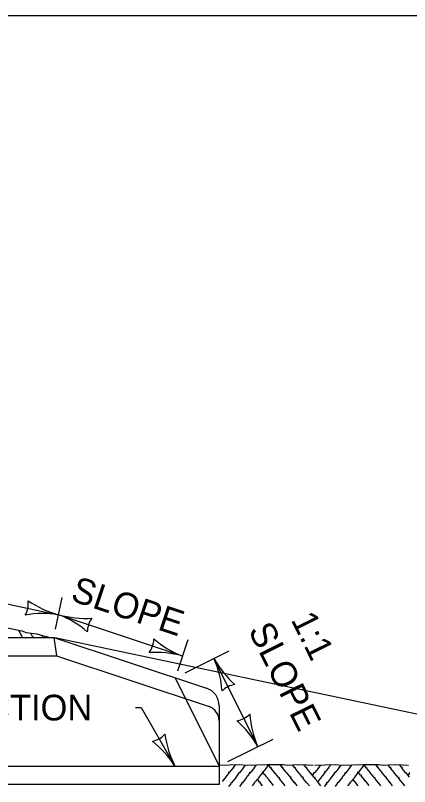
# Model space of a CAD drawing. Extents: x 49991.4 to 50022.1, y 49985 to 50011.4.
# Drawn here: x 50005.853 to 50006.771, y 49997.203 to 49998.999 of the extents above; entities that cross this region are included whole.
import ezdxf

# ---------------------------------------------------------------- set-up
doc = ezdxf.new("R2010")
doc.units = 0
for name, color, linetype in [('Level 1', 7, 'Continuous'), ('Level 2', 7, 'Continuous'), ('Level 3', 7, 'Continuous'), ('Level 4', 7, 'Continuous')]:
    doc.layers.add(name, color=color, linetype=linetype)

msp = doc.modelspace()

# ---------------------------------------------------------------- linework, layer by layer
at = {"layer": 'Level 1'}
for p, q in [((50003.702, 49997.5504), (50005.9421, 49997.5504)), ((50005.9421, 49997.5504), (50006.2981, 49997.4318)), ((50006.3273, 49997.3911), (50006.3273, 49997.208)), ((50006.3273, 49997.208), (50003.702, 49997.208))]:
    msp.add_line(p, q, dxfattribs=at)
msp.add_lwpolyline([(49999.3835, 49998.9992), (50016.7501, 49998.9992), (50016.7501, 49987.7988), (49999.3835, 49987.7988)], close=True, dxfattribs=at)
for points in [[(50005.7214, 49997.5944), (50005.7679, 49997.5866), (50005.785, 49997.5809), (50005.83, 49997.5731), (50005.8678, 49997.5653), (50005.8779, 49997.5617), (50005.9026, 49997.5584), (50005.9212, 49997.5532), (50005.9355, 49997.5494)], [(50005.8697, 49997.5486), (50005.8653, 49997.5572), (50005.866, 49997.559), (50005.8642, 49997.5593), (50005.8606, 49997.5668)], [(50005.8943, 49997.5486), (50005.8935, 49997.5506), (50005.8942, 49997.5522), (50005.8923, 49997.5526), (50005.8888, 49997.5602)], [(50005.9177, 49997.5486), (50005.9146, 49997.5552)], [(50006.3278, 49997.2526), (50006.375, 49997.2545), (50006.3929, 49997.2526), (50006.4385, 49997.2541), (50006.4769, 49997.2543), (50006.4876, 49997.2529), (50006.5126, 49997.2545), (50006.5318, 49997.2535), (50006.5465, 49997.2526)], [(50006.3658, 49997.2543), (50006.3598, 49997.2471), (50006.3605, 49997.2455), (50006.359, 49997.2455), (50006.3516, 49997.2361), (50006.3496, 49997.2361), (50006.35, 49997.2345), (50006.3422, 49997.2249), (50006.3422, 49997.2229), (50006.3406, 49997.2225), (50006.3344, 49997.2145)], [(50006.3882, 49997.2525), (50006.3827, 49997.2459), (50006.3836, 49997.2443), (50006.3821, 49997.2443), (50006.3746, 49997.2349), (50006.3726, 49997.2349), (50006.3728, 49997.2331), (50006.3652, 49997.2235), (50006.3652, 49997.2215), (50006.3636, 49997.2211), (50006.3562, 49997.2115), (50006.3545, 49997.2115), (50006.3548, 49997.2095), (50006.3496, 49997.2033)], [(50006.4139, 49997.2533), (50006.4079, 49997.246), (50006.4086, 49997.2445), (50006.4072, 49997.2445), (50006.3998, 49997.2351), (50006.3977, 49997.2351), (50006.398, 49997.2333), (50006.3905, 49997.2237), (50006.3905, 49997.222), (50006.3887, 49997.2213), (50006.3815, 49997.2119), (50006.3796, 49997.2117), (50006.38, 49997.21), (50006.3748, 49997.2034)], [(50006.4433, 49997.2541), (50006.4373, 49997.2469), (50006.438, 49997.2454), (50006.4367, 49997.2454), (50006.4292, 49997.2361), (50006.4274, 49997.2361), (50006.4276, 49997.2341), (50006.4199, 49997.2245), (50006.4199, 49997.2229), (50006.4182, 49997.2221), (50006.4109, 49997.2129), (50006.4092, 49997.2125), (50006.4094, 49997.2109), (50006.4043, 49997.2045)], [(50006.4817, 49997.2045), (50006.4769, 49997.2107), (50006.4754, 49997.2105), (50006.4757, 49997.2119), (50006.4682, 49997.2211), (50006.4686, 49997.2231), (50006.4667, 49997.2231), (50006.4592, 49997.2329), (50006.4574, 49997.2333), (50006.4572, 49997.2349), (50006.4498, 49997.2443), (50006.4499, 49997.246), (50006.4481, 49997.2461), (50006.443, 49997.2527)], [(50006.5092, 49997.2049), (50006.5036, 49997.2123), (50006.5018, 49997.2119), (50006.5022, 49997.2135), (50006.4948, 49997.2227), (50006.495, 49997.2245), (50006.4934, 49997.2249), (50006.4858, 49997.2345), (50006.4841, 49997.2347), (50006.4838, 49997.2365), (50006.4762, 49997.2459), (50006.4766, 49997.2477), (50006.4746, 49997.2477), (50006.4696, 49997.2543)], [(50006.5378, 49997.2045), (50006.5322, 49997.2115), (50006.5308, 49997.2113), (50006.531, 49997.2125), (50006.5236, 49997.222), (50006.524, 49997.2239), (50006.522, 49997.2241), (50006.5146, 49997.2335), (50006.5128, 49997.234), (50006.5126, 49997.2359), (50006.5051, 49997.2451), (50006.5052, 49997.2469), (50006.5036, 49997.2469), (50006.4985, 49997.2535)], [(50006.5483, 49997.2249), (50006.5412, 49997.2339), (50006.5396, 49997.2341), (50006.5393, 49997.2359), (50006.5316, 49997.2453), (50006.5321, 49997.2471), (50006.5302, 49997.2471), (50006.5249, 49997.2539)], [(50006.5639, 49997.2531), (50006.5579, 49997.246), (50006.5586, 49997.2445), (50006.5572, 49997.2445), (50006.5496, 49997.2351), (50006.5488, 49997.2351)], [(50006.5506, 49997.2526), (50006.5978, 49997.2545), (50006.6156, 49997.2526), (50006.6612, 49997.2541), (50006.6996, 49997.2543), (50006.7103, 49997.2529), (50006.7352, 49997.2545), (50006.7544, 49997.2535), (50006.7692, 49997.2526)], [(50006.5885, 49997.2543), (50006.5825, 49997.2471), (50006.5832, 49997.2455), (50006.5818, 49997.2455), (50006.5744, 49997.2361), (50006.5723, 49997.2361), (50006.5728, 49997.2345), (50006.5651, 49997.2249), (50006.5651, 49997.2229), (50006.5633, 49997.2225), (50006.5573, 49997.2145)], [(50006.611, 49997.2525), (50006.6056, 49997.2459), (50006.606, 49997.2443), (50006.6047, 49997.2443), (50006.5972, 49997.2349), (50006.5954, 49997.2349), (50006.5956, 49997.2331), (50006.5879, 49997.2235), (50006.5879, 49997.2215), (50006.5864, 49997.2211), (50006.579, 49997.2115), (50006.5772, 49997.2115), (50006.5776, 49997.2095), (50006.5723, 49997.2033)], [(50006.6366, 49997.2533), (50006.6306, 49997.246), (50006.6314, 49997.2445), (50006.6299, 49997.2445), (50006.6224, 49997.2351), (50006.6206, 49997.2351), (50006.6209, 49997.2333), (50006.6131, 49997.2237), (50006.6131, 49997.222), (50006.6116, 49997.2213), (50006.6042, 49997.2119), (50006.6023, 49997.2117), (50006.6028, 49997.21), (50006.5975, 49997.2034)], [(50006.666, 49997.2541), (50006.66, 49997.2469), (50006.6608, 49997.2454), (50006.6596, 49997.2454), (50006.6521, 49997.2361), (50006.6502, 49997.2361), (50006.6503, 49997.2341), (50006.6426, 49997.2245), (50006.6426, 49997.2229), (50006.641, 49997.2221), (50006.6336, 49997.2129), (50006.632, 49997.2125), (50006.6323, 49997.2109), (50006.627, 49997.2045)], [(50006.7046, 49997.2045), (50006.6998, 49997.2107), (50006.6982, 49997.2105), (50006.6986, 49997.2119), (50006.6911, 49997.2211), (50006.6914, 49997.2231), (50006.6896, 49997.2231), (50006.6821, 49997.2329), (50006.6803, 49997.2333), (50006.68, 49997.2349), (50006.6725, 49997.2443), (50006.6728, 49997.246), (50006.671, 49997.2461), (50006.6659, 49997.2527)], [(50006.7318, 49997.2049), (50006.7262, 49997.2123), (50006.7246, 49997.2119), (50006.725, 49997.2135), (50006.7175, 49997.2227), (50006.7178, 49997.2245), (50006.7162, 49997.2249), (50006.7085, 49997.2345), (50006.7067, 49997.2347), (50006.7066, 49997.2365), (50006.6989, 49997.2459), (50006.6992, 49997.2477), (50006.6974, 49997.2477), (50006.6923, 49997.2543)], [(50006.7606, 49997.2045), (50006.755, 49997.2115), (50006.7535, 49997.2113), (50006.7538, 49997.2125), (50006.7463, 49997.222), (50006.7468, 49997.2239), (50006.7448, 49997.2241), (50006.7373, 49997.2335), (50006.7355, 49997.234), (50006.7352, 49997.2359), (50006.7277, 49997.2451), (50006.7282, 49997.2469), (50006.7262, 49997.2469), (50006.7212, 49997.2535)], [(50006.771, 49997.2249), (50006.764, 49997.2339), (50006.7622, 49997.2341), (50006.762, 49997.2359), (50006.7544, 49997.2453), (50006.7547, 49997.2471), (50006.7529, 49997.2471), (50006.7475, 49997.2539)], [(50006.4542, 49997.2053), (50006.4456, 49997.2161), (50006.4439, 49997.2166), (50006.4438, 49997.2184), (50006.4362, 49997.2275), (50006.4364, 49997.2295), (50006.4346, 49997.2295), (50006.4296, 49997.2359)], [(50006.5486, 49997.2351), (50006.5476, 49997.2351), (50006.5477, 49997.2333), (50006.545, 49997.2297)], [(50006.677, 49997.2053), (50006.6683, 49997.2161), (50006.6666, 49997.2166), (50006.6665, 49997.2184), (50006.659, 49997.2275), (50006.6592, 49997.2295), (50006.6572, 49997.2295), (50006.6524, 49997.2359)], [(50006.7712, 49997.2351), (50006.7703, 49997.2351), (50006.7706, 49997.2333), (50006.7678, 49997.2297)], [(50006.4286, 49997.2047), (50006.4232, 49997.2115), (50006.4235, 49997.2131), (50006.4216, 49997.2135), (50006.4166, 49997.2199)], [(50006.5648, 49997.2046), (50006.5594, 49997.2117), (50006.5578, 49997.2113), (50006.558, 49997.2129), (50006.5506, 49997.2221), (50006.551, 49997.2241), (50006.5492, 49997.2243), (50006.5488, 49997.2249)], [(50006.6512, 49997.2047), (50006.6461, 49997.2115), (50006.6462, 49997.2131), (50006.6443, 49997.2135), (50006.6392, 49997.2199)]]:
    msp.add_lwpolyline(points, dxfattribs=at)
msp.add_arc((50006.2846, 49997.3912), 0.0428, 0, 71.5416, dxfattribs=at)
at = {"layer": 'Level 3'}
for p, q in [((50004.934, 49997.8178), (50005.9533, 49997.6033)), ((50005.9462, 49997.5698), (50005.9617, 49997.6431)), ((50006.242, 49997.507), (50005.9533, 49997.6033)), ((50006.2547, 49997.545), (50006.2301, 49997.4714)), ((50006.2479, 49997.4675), (50006.3511, 49997.519)), ((50006.3153, 49997.5011), (50006.4177, 49997.2958)), ((50006.1322, 49997.3869), (50006.1458, 49997.3869)), ((50006.1458, 49997.3869), (50006.2244, 49997.2508)), ((50006.348, 49997.2611), (50006.4536, 49997.3137))]:
    msp.add_line(p, q, dxfattribs=at)
for centre, radius, start, end in [((50005.8278, 49997.6297), 0.0548, 330.2525, 5.9749), ((50006.008, 49997.8188), 0.2223, 235.5697, 255.7532), ((50005.9166, 49997.3732), 0.233, 80.941, 100.1908), ((50005.8743, 49997.3954), 0.2223, 49.0151, 69.1986), ((50006.016, 49997.8277), 0.233, 254.3864, 273.6363), ((50006.0749, 49997.5627), 0.0548, 143.6979, 179.4203), ((50006.1204, 49997.5476), 0.0548, 323.6979, 359.4203), ((50006.321, 49997.7148), 0.2223, 229.0151, 249.1986), ((50006.1793, 49997.2826), 0.233, 74.3864, 93.6363), ((50006.1124, 49997.4102), 0.2223, 3.9652, 24.1487), ((50006.5184, 49997.6153), 0.233, 209.3365, 228.5864), ((50006.3725, 49997.3864), 0.0548, 98.648, 134.3704), ((50006.3605, 49997.4105), 0.0548, 278.648, 314.3704), ((50006.6206, 49997.3868), 0.2223, 183.9652, 204.1487), ((50006.2146, 49997.1817), 0.233, 29.3365, 48.5864), ((50006.1603, 49997.3618), 0.0548, 282.1378, 317.8602), ((50006.4214, 49997.3539), 0.2223, 187.455, 207.6385), ((50006.0286, 49997.1245), 0.233, 32.8263, 52.0762)]:
    msp.add_arc(centre, radius, start, end, dxfattribs=at)
at = {"layer": 'Level 4'}
for p, q in [((50005.9421, 49997.5504), (50005.9483, 49997.5077)), ((50005.9442, 49997.55), (50007.3483, 49997.2547)), ((50003.702, 49997.5077), (50005.9483, 49997.5077)), ((50005.9483, 49997.5077), (50006.304, 49997.3891)), ((50006.2251, 49997.4561), (50006.3273, 49997.2508)), ((50003.702, 49997.2508), (50006.3273, 49997.2508))]:
    msp.add_line(p, q, dxfattribs=at)
msp.add_arc((50006.2931, 49997.3566), 0.0342, 0, 71.5749, dxfattribs=at)

# ---------------------------------------------------------------- texts
at = {"layer": 'Level 2'}
for s, rotation, p in [('SLOPE', 341.5752, (50005.9786, 49997.637)), (' 1:1', 296.4886, (50006.4838, 49997.6116)), ('SLOPE', 296.4886, (50006.3943, 49997.567))]:
    msp.add_text(s, height=0.06, rotation=rotation, dxfattribs=at).set_placement(p)
msp.add_text('END SECTION', height=0.06, dxfattribs=at).set_placement((50005.4832, 49997.3569))

doc.saveas('drawing.dxf')
